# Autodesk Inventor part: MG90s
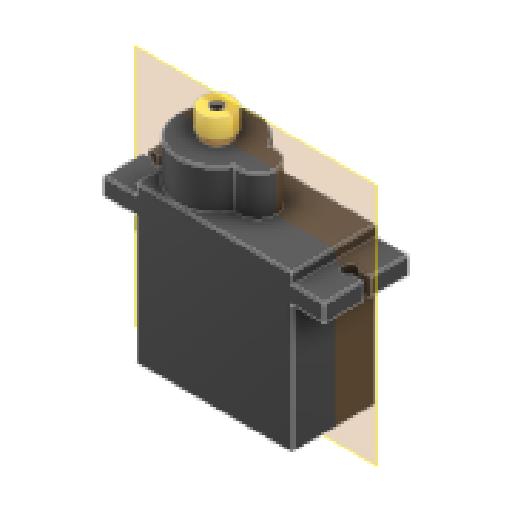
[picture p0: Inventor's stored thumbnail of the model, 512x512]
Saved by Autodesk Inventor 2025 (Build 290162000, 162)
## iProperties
Created: 2022-09
Part Number: MG90s
Material: Generico
Document SubType Name: Modeling
Designer: admin
Density: 1 g/cm^3
Appearance: Default
Author: admin
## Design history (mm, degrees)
feature "Solid1"
node "Piano di lavoro1"
node "Solido1"
